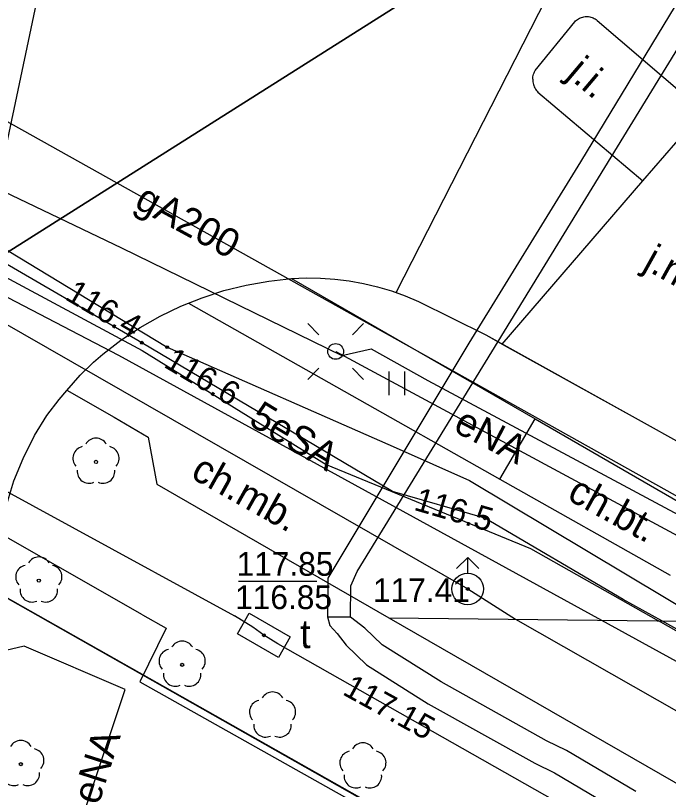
# Model space of a CAD drawing. Extents: x 6434771 to 6436222, y 5663454 to 5664782.
# Drawn here: x 6435079.09 to 6435099.76, y 5663940.88 to 5663965.39 of the extents above; entities that cross this region are included whole.
import ezdxf

# ---------------------------------------------------------------- set-up
doc = ezdxf.new("R2010")
doc.units = 0
for name, color, linetype in [('Warstwa 1', 7, 'Continuous'), ('Warstwa 10', 7, 'Continuous'), ('Warstwa 11', 7, 'Continuous'), ('Warstwa 12', 7, 'Continuous'), ('Warstwa 13', 7, 'Continuous'), ('Warstwa 14', 7, 'Continuous'), ('Warstwa 2', 7, 'Continuous'), ('Warstwa 4', 7, 'Continuous'), ('Warstwa 5', 7, 'Continuous'), ('Warstwa 6', 7, 'Continuous'), ('Warstwa 7', 7, 'Continuous'), ('Warstwa 8', 7, 'Continuous'), ('Warstwa 9', 7, 'Continuous')]:
    doc.layers.add(name, color=color, linetype=linetype)

msp = doc.modelspace()

# ---------------------------------------------------------------- linework, layer by layer
at = {"layer": 'Warstwa 1'}
for q in [(6435120.043, 5663983.972), (6435120.043, 5663983.972), (6435199.169, 5663878.85), (6435199.169, 5663878.85)]:
    msp.add_line((6435069.683, 5663952.11), q, dxfattribs=at)
at = {"layer": 'Warstwa 10'}
for points in [[(6434896.42, 5664071.06), (6434898.16, 5664073.03), (6434900.23, 5664072.06), (6434923.31, 5664061.23), (6434926.55, 5664059.81), (6434927.25, 5664060), (6434930.24, 5664058.57), (6434930.73, 5664057.88), (6434948.57, 5664048.49), (6434986.66, 5664027.63), (6435008.6, 5664015.27), (6435029.24, 5664003.72), (6435037.15, 5663998.25), (6435049.94, 5663990.19), (6435056.65, 5663985.18), (6435065.79, 5663976.31), (6435067.86, 5663972.11), (6435071.01, 5663962.36), (6435072.82, 5663959.6), (6435082.35, 5663954.64), (6435097.639, 5663946.244)], [(6435029.359, 5664004.111), (6435038.639, 5663997.479), (6435049.682, 5663991.014), (6435059.257, 5663983.908), (6435063.578, 5663979.846), (6435066.7, 5663975.848), (6435068.234, 5663972.039), (6435070.123, 5663963.685), (6435072.703, 5663960.364), (6435083.097, 5663954.788), (6435088.923, 5663951.177), (6435095.392, 5663948.519), (6435099.449, 5663946.22)], [(6435099.552, 5663946.221), (6435098.33, 5663946.9), (6435093.95, 5663949.47), (6435091.03, 5663950.32), (6435083.09, 5663955.03), (6435073.14, 5663960.81), (6435072.01, 5663961.77), (6435069.49, 5663965.07), (6435065.5, 5663971.7), (6435061.58, 5663976.4), (6435056.94, 5663981.63), (6435044.61, 5663991.64), (6435039.27, 5663995.38), (6435030.2, 5664000.49)], [(6435097.639, 5663946.244), (6435110.23, 5663939.33), (6435134.8, 5663925.67), (6435154.54, 5663914.28), (6435171.5, 5663904.82), (6435193.4, 5663892.21), (6435192.998, 5663890.805)], [(6435182.257, 5663838.676), (6435188.304, 5663849.448), (6435193.351, 5663858.439), (6435194.278, 5663859.798), (6435191.577, 5663860.571), (6435190.64, 5663861.662), (6435194.242, 5663871.739), (6435194.776, 5663876.163), (6435192.223, 5663879.254), (6435189.657, 5663881.265), (6435188.718, 5663882.987), (6435189.733, 5663885.054), (6435194.267, 5663892.79), (6435145.165, 5663920.315), (6435099.449, 5663946.22)], [(6435276.336, 5663842.501), (6435260.05, 5663851.86), (6435249.96, 5663857.64), (6435238.71, 5663863.53), (6435238.1, 5663863.95), (6435237.79, 5663864.33), (6435236.77, 5663866.27), (6435229, 5663870.99), (6435224.85, 5663875.36), (6435224.07, 5663876.18), (6435215.14, 5663881.13), (6435208.14, 5663884.9), (6435192.12, 5663893.65), (6435170.67, 5663905.68), (6435152.15, 5663915.89), (6435146.79, 5663915.59), (6435128.02, 5663926.23), (6435125.23, 5663931.72), (6435111.04, 5663939.84), (6435099.552, 5663946.221)]]:
    msp.add_lwpolyline(points, dxfattribs=at)
at = {"layer": 'Warstwa 11'}
for centre in [(6435081.638, 5663951.256), (6435079.828, 5663947.497), (6435084.366, 5663944.832), (6435079.257, 5663941.684)]:
    msp.add_circle(centre, 0.05, dxfattribs=at)
for centre, start, end in [((6435081.638, 5663951.631), 30.1471, 149.8529), ((6435081.281, 5663951.372), 102.1471, 221.8529), ((6435081.995, 5663951.372), 318.1471, 77.8529), ((6435081.418, 5663950.953), 174.1471, 293.8529), ((6435081.858, 5663950.953), 246.1471, 5.8529), ((6435079.828, 5663947.872), 30.1471, 149.8529), ((6435079.471, 5663947.613), 102.1471, 221.8529), ((6435080.185, 5663947.613), 318.1471, 77.8529), ((6435079.608, 5663947.194), 174.1471, 293.8529), ((6435080.048, 5663947.194), 246.1471, 5.8529), ((6435084.366, 5663945.207), 30.1471, 149.8529), ((6435084.009, 5663944.948), 102.1471, 221.8529), ((6435084.723, 5663944.948), 318.1471, 77.8529), ((6435084.146, 5663944.529), 174.1471, 293.8529), ((6435084.586, 5663944.529), 246.1471, 5.8529), ((6435079.257, 5663942.059), 30.1471, 149.8529), ((6435079.614, 5663941.8), 318.1471, 77.8529), ((6435079.037, 5663941.381), 174.1471, 293.8529), ((6435079.477, 5663941.381), 246.1471, 5.8529)]:
    msp.add_arc(centre, 0.375, start, end, dxfattribs=at)
at = {"layer": 'Warstwa 12'}
for points in [[(6435141, 5664096.944), (6435140.712, 5664094.875), (6435140.541, 5664077.81), (6435140.348, 5664058.843), (6435140.244, 5664037.853), (6435131.538, 5664021.545), (6435121.662, 5664002.962), (6435115.163, 5663990.896), (6435113.532, 5663987.769), (6435105.974, 5663975.592), (6435096.975, 5663960.761), (6435093.444, 5663955.018), (6435088.979, 5663947.571), (6435088.964, 5663946.347), (6435089.697, 5663946.338), (6435089.709, 5663947.336), (6435089.904, 5663947.79), (6435099.437, 5663963.329), (6435112.073, 5663983.894), (6435114.868, 5663988.39), (6435124.041, 5664005.528), (6435134.579, 5664025.286), (6435141.037, 5664037.344)], [(6434986.93, 5664031.717), (6434992.77, 5664028.437), (6435004.492, 5664021.894), (6435005.105, 5664018.185), (6435011.542, 5664014.684), (6435027.829, 5664005.549), (6435040.87, 5663998.248), (6435044.067, 5663996.463), (6435047.835, 5663993.916), (6435060.611, 5663984.964), (6435069.684, 5663978.472), (6435072.37, 5663972.912), (6435073.728, 5663967.815), (6435073.844, 5663967.084), (6435073.839, 5663962.379), (6435073.912, 5663958.232), (6435075.469, 5663957.501), (6435076.211, 5663957.1), (6435093.406, 5663947.233)], [(6435029.763, 5664005.454), (6435034.388, 5664002.299), (6435042.886, 5663996.481), (6435048.366, 5663992.784), (6435050.056, 5663992.458), (6435053.785, 5663989.318), (6435060.963, 5663983.658), (6435062.158, 5663982.516), (6435067.739, 5663976.436), (6435069.698, 5663972.561), (6435070.863, 5663972.195), (6435071.455, 5663970.037), (6435072.977, 5663964.049), (6435072.957, 5663962.572), (6435082.449, 5663958.039), (6435089.417, 5663954.626), (6435090.354, 5663954.835), (6435092.145, 5663953.831), (6435102.441, 5663948.316), (6435106.279, 5663946.137)], [(6435065.567, 5663979.291), (6435066.099, 5663979.065), (6435068.636, 5663973.044), (6435071.308, 5663958.281), (6435070.678, 5663955.808), (6435070.482, 5663955.351), (6435070.596, 5663954.809), (6435086.024, 5663946.382)], [(6435076.981, 5663977.987), (6435075.009, 5663964.166), (6435107.26, 5663946.125)], [(6435062.844, 5663975.005), (6435065.937, 5663971.01), (6435067.536, 5663968.978), (6435072.283, 5663961.757), (6435073.425, 5663961.235), (6435081.75, 5663956.189), (6435083.889, 5663954.89), (6435091.142, 5663951.702), (6435093.466, 5663950.667), (6435100.922, 5663946.202)], [(6435089.227, 5663954.754), (6435105.187, 5663946.15)], [(6435093.406, 5663947.233), (6435094.917, 5663946.274)], [(6435079.194, 5663933.129), (6435079.1, 5663933.665), (6435082.557, 5663944.054), (6435079.363, 5663945.423), (6435077.427, 5663944.966), (6435072.67, 5663946.544)], [(6435276.296, 5663839.122), (6435202.248, 5663880.463), (6435193.528, 5663885.439), (6435193.106, 5663885.714), (6435192.653, 5663885.899), (6435159.975, 5663904.455), (6435111.809, 5663931.659), (6435087.394, 5663945.495), (6435086.953, 5663945.766), (6435086.601, 5663946.025), (6435086.024, 5663946.382)], [(6435098.725, 5663940.821), (6435096.535, 5663942.118), (6435095.902, 5663942.428), (6435092.567, 5663944.288), (6435090.696, 5663945.465), (6435090.154, 5663945.991), (6435089.697, 5663946.338), (6435088.964, 5663946.347), (6435089.045, 5663946.075), (6435089.273, 5663945.821), (6435089.556, 5663945.455), (6435090.2, 5663944.833), (6435092.159, 5663943.6), (6435095.532, 5663941.718), (6435096.155, 5663941.414), (6435098.325, 5663940.127)], [(6435094.917, 5663946.274), (6435142.273, 5663919.31), (6435142.316, 5663919.287), (6435154.155, 5663912.836)]]:
    msp.add_lwpolyline(points, dxfattribs=at)
at = {"layer": 'Warstwa 13'}
for centre, start, end in [((6435087.227, 5663943.596), 30.1471, 149.8529), ((6435086.87, 5663943.337), 102.0477, 221.9513), ((6435087.584, 5663943.337), 318.0487, 77.9523), ((6435087.007, 5663942.918), 174.1984, 293.7229), ((6435087.447, 5663942.918), 246.2771, 5.6877), ((6435090.088, 5663941.985), 30.1471, 149.8529), ((6435089.731, 5663941.726), 102.0477, 221.9513), ((6435090.445, 5663941.726), 318.0487, 77.9523), ((6435089.868, 5663941.307), 174.1984, 293.7229), ((6435090.308, 5663941.307), 246.2771, 5.6877)]:
    msp.add_arc(centre, 0.375, start, end, dxfattribs=at)
at = {"layer": 'Warstwa 14'}
msp.add_line((6435086.149, 5663947.482), (6435088.624, 5663947.482), dxfattribs=at)
for centre in [(6435083.09, 5663955.03), (6435083.889, 5663954.89), (6435093.95, 5663949.47), (6435086.953, 5663945.766), (6435086.953, 5663945.766)]:
    msp.add_circle(centre, 0.045, dxfattribs=at)
at = {"layer": 'Warstwa 2'}
for points in [[(6435083.106, 5663946.417), (6435077.742, 5663949.472)], [(6435083.106, 5663946.417), (6435083.86, 5663945.988), (6435083.029, 5663944.288), (6435118.054, 5663924.603)]]:
    msp.add_lwpolyline(points, dxfattribs=at)
msp.add_circle((6435089.227, 5663954.754), 0.25, dxfattribs=at)
at = {"layer": 'Warstwa 4'}
for points in [[(6435088.697, 5663955.284), (6435088.343, 5663955.638)], [(6435089.757, 5663955.284), (6435090.111, 5663955.638)], [(6435088.697, 5663954.224), (6435088.343, 5663953.87)], [(6435089.757, 5663954.224), (6435090.111, 5663953.87)], [(6435093.052, 5663947.879), (6435093.406, 5663948.233)], [(6435093.76, 5663947.879), (6435093.406, 5663948.233)], [(6435093.406, 5663947.733), (6435093.406, 5663948.233)]]:
    msp.add_lwpolyline(points, dxfattribs=at)
msp.add_lwpolyline([(6435086.116, 5663945.813), (6435086.488, 5663946.464), (6435087.79, 5663945.719), (6435087.418, 5663945.068)], close=True, dxfattribs=at)
msp.add_circle((6435093.406, 5663947.233), 0.5, dxfattribs=at)
at = {"layer": 'Warstwa 5'}
for p, q in [((6435086.392, 5663956.856), (6435087.108, 5663956.983)), ((6435087.108, 5663956.983), (6435087.831, 5663957.061)), ((6435087.831, 5663957.061), (6435095.541, 5663952.617)), ((6435085.686, 5663956.68), (6435086.392, 5663956.856)), ((6435084.564, 5663956.284), (6435084.994, 5663956.456)), ((6435084.994, 5663956.456), (6435085.686, 5663956.68)), ((6435084.564, 5663956.284), (6435094.428, 5663950.711)), ((6435090.918, 5663953.368), (6435090.918, 5663954.118)), ((6435091.418, 5663953.368), (6435091.418, 5663954.118)), ((6435094.428, 5663950.711), (6435095.541, 5663952.617))]:
    msp.add_line(p, q, dxfattribs=at)
at = {"layer": 'Warstwa 6'}
for points in [[(6435199.169, 5663878.85), (6435069.683, 5663952.11), (6435070.435, 5663958.091), (6435069.483, 5663961.233), (6435068.325, 5663963.837), (6435062.043, 5663974.514), (6435058.095, 5663979.622), (6435055.831, 5663981.839), (6435050.759, 5663985.791), (6435026.957, 5664002.35), (6434999.334, 5664017.996), (6434991.09, 5664022.666), (6434980.58, 5664028.593), (6434951.952, 5664044.671), (6434942.859, 5664049.431), (6434933.864, 5664054.041), (6434925.132, 5664058.117), (6434918.181, 5664061.441), (6434909.328, 5664065.359), (6434902.911, 5664068.147), (6434896.533, 5664070.874)], [(6435305.06, 5663883.021), (6435273.017, 5663901.219), (6435268.258, 5663903.897), (6435244.547, 5663917.184), (6435243.096, 5663914.681), (6435163.64, 5663959.364), (6435156.428, 5663963.391), (6435120.043, 5663983.972), (6435069.683, 5663952.11), (6435199.169, 5663878.85)], [(6435081.849, 5663954.665), (6435082.426, 5663955.108), (6435083.032, 5663955.51), (6435083.664, 5663955.87), (6435084.319, 5663956.186), (6435084.994, 5663956.456), (6435085.686, 5663956.68), (6435086.392, 5663956.856), (6435087.108, 5663956.983), (6435087.831, 5663957.061)], [(6435087.831, 5663957.061), (6435088.288, 5663957.082), (6435088.746, 5663957.077), (6435089.203, 5663957.046), (6435089.658, 5663956.99), (6435090.109, 5663956.909), (6435090.555, 5663956.803), (6435090.994, 5663956.672), (6435091.425, 5663956.517), (6435091.847, 5663956.338)], [(6435091.847, 5663956.338), (6435093.976, 5663955.277), (6435098.798, 5663952.598), (6435100.211, 5663951.818), (6435101.536, 5663951.115), (6435104.703, 5663949.243), (6435106.032, 5663948.42), (6435107.739, 5663947.509), (6435110.04, 5663946.091)], [(6435078.616, 5663949.002), (6435078.849, 5663950.027), (6435079.035, 5663950.655), (6435079.334, 5663951.359), (6435079.688, 5663952.096), (6435080.078, 5663952.721), (6435080.474, 5663953.236), (6435080.712, 5663953.521), (6435081.141, 5663954.002), (6435081.558, 5663954.418), (6435081.849, 5663954.665)]]:
    msp.add_lwpolyline(points, dxfattribs=at)
msp.add_lwpolyline([(6435026.957, 5664002.35), (6435050.759, 5663985.791), (6435055.831, 5663981.839), (6435058.095, 5663979.622), (6435062.043, 5663974.514), (6435068.325, 5663963.837), (6435069.483, 5663961.233), (6435070.435, 5663958.091), (6435069.683, 5663952.11), (6435120.043, 5663983.972), (6435070.884, 5664005.038), (6435011.285, 5664038.642), (6434957.736, 5664068.872), (6434942.859, 5664049.431), (6434951.952, 5664044.671), (6434980.58, 5664028.593), (6434991.09, 5664022.666), (6434999.334, 5664017.996)], close=True, dxfattribs=at)
for centre in [(6435093.406, 5663947.233), (6435086.953, 5663945.766)]:
    msp.add_circle(centre, 0.045, dxfattribs=at)
at = {"layer": 'Warstwa 7'}
msp.add_lwpolyline([(6435092.414, 5663987.68), (6435084.106, 5663975.052), (6435081.187, 5663970.512), (6435080.599, 5663969.849), (6435075.668, 5663946.507)], dxfattribs=at)
at = {"layer": 'Warstwa 8'}
for p, q in [((6435091.144, 5663956.618), (6435099.409, 5663972.815)), ((6435091.144, 5663956.618), (6435099.409, 5663972.815)), ((6435096.881, 5663965.265), (6435096.912, 5663965.285)), ((6435096.881, 5663965.265), (6435096.912, 5663965.285)), ((6435096.912, 5663965.285), (6435096.945, 5663965.303)), ((6435096.912, 5663965.285), (6435096.945, 5663965.303)), ((6435096.945, 5663965.303), (6435096.979, 5663965.319)), ((6435096.945, 5663965.303), (6435096.979, 5663965.319)), ((6435096.979, 5663965.319), (6435097.014, 5663965.332)), ((6435096.979, 5663965.319), (6435097.014, 5663965.332)), ((6435097.014, 5663965.332), (6435097.05, 5663965.343)), ((6435097.014, 5663965.332), (6435097.05, 5663965.343)), ((6435097.05, 5663965.343), (6435097.086, 5663965.351)), ((6435097.05, 5663965.343), (6435097.086, 5663965.351)), ((6435097.086, 5663965.351), (6435097.123, 5663965.356)), ((6435097.086, 5663965.351), (6435097.123, 5663965.356)), ((6435097.123, 5663965.356), (6435097.16, 5663965.359)), ((6435097.123, 5663965.356), (6435097.16, 5663965.359)), ((6435097.16, 5663965.359), (6435097.198, 5663965.359)), ((6435097.16, 5663965.359), (6435097.198, 5663965.359)), ((6435097.198, 5663965.359), (6435097.235, 5663965.356)), ((6435097.198, 5663965.359), (6435097.235, 5663965.356)), ((6435097.235, 5663965.356), (6435097.272, 5663965.35)), ((6435097.235, 5663965.356), (6435097.272, 5663965.35)), ((6435097.272, 5663965.35), (6435097.308, 5663965.342)), ((6435097.272, 5663965.35), (6435097.308, 5663965.342)), ((6435097.308, 5663965.342), (6435097.344, 5663965.331)), ((6435097.308, 5663965.342), (6435097.344, 5663965.331)), ((6435097.344, 5663965.331), (6435097.379, 5663965.317)), ((6435097.344, 5663965.331), (6435097.379, 5663965.317)), ((6435097.379, 5663965.317), (6435097.412, 5663965.301)), ((6435097.379, 5663965.317), (6435097.412, 5663965.301)), ((6435097.412, 5663965.301), (6435097.445, 5663965.282)), ((6435097.412, 5663965.301), (6435097.445, 5663965.282)), ((6435097.445, 5663965.282), (6435097.476, 5663965.261)), ((6435097.445, 5663965.282), (6435097.476, 5663965.261)), ((6435095.542, 5663963.645), (6435096.798, 5663965.19)), ((6435095.542, 5663963.645), (6435096.798, 5663965.19)), ((6435096.798, 5663965.19), (6435096.824, 5663965.217)), ((6435096.798, 5663965.19), (6435096.824, 5663965.217)), ((6435096.824, 5663965.217), (6435096.852, 5663965.242)), ((6435096.824, 5663965.217), (6435096.852, 5663965.242)), ((6435096.852, 5663965.242), (6435096.881, 5663965.265)), ((6435096.852, 5663965.242), (6435096.881, 5663965.265)), ((6435097.476, 5663965.261), (6435097.505, 5663965.238)), ((6435097.476, 5663965.261), (6435097.505, 5663965.238)), ((6435097.505, 5663965.238), (6435100.854, 5663962.363)), ((6435097.505, 5663965.238), (6435100.854, 5663962.363)), ((6435095.491, 5663963.533), (6435095.505, 5663963.572)), ((6435095.491, 5663963.533), (6435095.505, 5663963.572)), ((6435095.505, 5663963.572), (6435095.522, 5663963.609)), ((6435095.505, 5663963.572), (6435095.522, 5663963.609)), ((6435095.522, 5663963.609), (6435095.542, 5663963.645)), ((6435095.522, 5663963.609), (6435095.542, 5663963.645)), ((6435095.464, 5663963.372), (6435095.466, 5663963.413)), ((6435095.464, 5663963.372), (6435095.466, 5663963.413)), ((6435095.464, 5663963.372), (6435095.464, 5663963.331)), ((6435095.464, 5663963.372), (6435095.464, 5663963.331)), ((6435095.464, 5663963.331), (6435095.468, 5663963.29)), ((6435095.464, 5663963.331), (6435095.468, 5663963.29)), ((6435095.466, 5663963.413), (6435095.471, 5663963.454)), ((6435095.466, 5663963.413), (6435095.471, 5663963.454)), ((6435095.471, 5663963.454), (6435095.48, 5663963.494)), ((6435095.471, 5663963.454), (6435095.48, 5663963.494)), ((6435095.48, 5663963.494), (6435095.491, 5663963.533)), ((6435095.48, 5663963.494), (6435095.491, 5663963.533)), ((6435095.468, 5663963.29), (6435095.475, 5663963.25)), ((6435095.468, 5663963.29), (6435095.475, 5663963.25)), ((6435095.475, 5663963.25), (6435095.484, 5663963.21)), ((6435095.475, 5663963.25), (6435095.484, 5663963.21)), ((6435095.484, 5663963.21), (6435095.497, 5663963.17)), ((6435095.484, 5663963.21), (6435095.497, 5663963.17)), ((6435095.497, 5663963.17), (6435095.512, 5663963.132)), ((6435095.497, 5663963.17), (6435095.512, 5663963.132)), ((6435095.512, 5663963.132), (6435095.53, 5663963.096)), ((6435095.512, 5663963.132), (6435095.53, 5663963.096)), ((6435095.53, 5663963.096), (6435095.551, 5663963.06)), ((6435095.53, 5663963.096), (6435095.551, 5663963.06)), ((6435095.551, 5663963.06), (6435095.574, 5663963.026)), ((6435095.551, 5663963.06), (6435095.574, 5663963.026)), ((6435095.574, 5663963.026), (6435095.6, 5663962.994)), ((6435095.574, 5663963.026), (6435095.6, 5663962.994)), ((6435095.6, 5663962.994), (6435095.628, 5663962.964)), ((6435095.6, 5663962.994), (6435095.628, 5663962.964)), ((6435095.628, 5663962.964), (6435098.953, 5663960.156)), ((6435095.628, 5663962.964), (6435098.953, 5663960.156)), ((6435098.953, 5663960.156), (6435100.854, 5663962.363)), ((6435098.953, 5663960.156), (6435100.854, 5663962.363)), ((6435094.5, 5663954.986), (6435098.953, 5663960.156)), ((6435094.5, 5663954.986), (6435098.953, 5663960.156)), ((6435086.392, 5663956.856), (6435087.108, 5663956.983)), ((6435087.108, 5663956.983), (6435087.831, 5663957.061)), ((6435087.831, 5663957.061), (6435088.288, 5663957.082)), ((6435088.288, 5663957.082), (6435088.746, 5663957.077)), ((6435088.746, 5663957.077), (6435089.203, 5663957.046)), ((6435089.203, 5663957.046), (6435089.658, 5663956.99)), ((6435089.658, 5663956.99), (6435090.109, 5663956.909)), ((6435085.686, 5663956.68), (6435086.392, 5663956.856)), ((6435090.109, 5663956.909), (6435090.555, 5663956.803)), ((6435090.555, 5663956.803), (6435090.994, 5663956.672)), ((6435084.319, 5663956.186), (6435084.994, 5663956.456)), ((6435084.994, 5663956.456), (6435085.686, 5663956.68)), ((6435090.994, 5663956.672), (6435091.144, 5663956.618)), ((6435091.144, 5663956.618), (6435091.425, 5663956.517)), ((6435091.425, 5663956.517), (6435091.847, 5663956.338)), ((6435091.847, 5663956.338), (6435093.976, 5663955.277)), ((6435083.664, 5663955.87), (6435084.319, 5663956.186)), ((6435083.032, 5663955.51), (6435083.664, 5663955.87)), ((6435082.426, 5663955.108), (6435083.032, 5663955.51)), ((6435093.976, 5663955.277), (6435094.5, 5663954.986)), ((6435081.849, 5663954.665), (6435082.426, 5663955.108)), ((6435094.5, 5663954.986), (6435098.798, 5663952.598)), ((6435081.558, 5663954.418), (6435081.849, 5663954.665)), ((6435081.141, 5663954.002), (6435081.558, 5663954.418)), ((6435080.716, 5663953.526), (6435081.141, 5663954.002)), ((6435080.474, 5663953.236), (6435080.712, 5663953.521)), ((6435080.712, 5663953.521), (6435080.716, 5663953.526)), ((6435080.078, 5663952.721), (6435080.474, 5663953.236)), ((6435079.688, 5663952.096), (6435080.078, 5663952.721)), ((6435098.798, 5663952.598), (6435100.211, 5663951.818)), ((6435079.334, 5663951.359), (6435079.688, 5663952.096)), ((6435079.035, 5663950.655), (6435079.334, 5663951.359))]:
    msp.add_line(p, q, dxfattribs=at)
at = {"layer": 'Warstwa 9'}
for p, q in [((6435087.831, 5663957.061), (6435088.288, 5663957.082)), ((6435087.831, 5663957.061), (6435095.541, 5663952.617)), ((6435088.288, 5663957.082), (6435088.746, 5663957.077)), ((6435088.746, 5663957.077), (6435089.203, 5663957.046)), ((6435089.203, 5663957.046), (6435089.658, 5663956.99)), ((6435089.658, 5663956.99), (6435090.109, 5663956.909)), ((6435090.109, 5663956.909), (6435090.555, 5663956.803)), ((6435090.555, 5663956.803), (6435090.994, 5663956.672)), ((6435090.994, 5663956.672), (6435091.144, 5663956.618)), ((6435091.144, 5663956.618), (6435091.425, 5663956.517)), ((6435091.425, 5663956.517), (6435091.847, 5663956.338)), ((6435084.319, 5663956.186), (6435084.564, 5663956.284)), ((6435084.564, 5663956.284), (6435094.428, 5663950.711)), ((6435091.847, 5663956.338), (6435093.976, 5663955.277)), ((6435083.664, 5663955.87), (6435084.319, 5663956.186)), ((6435083.032, 5663955.51), (6435083.664, 5663955.87)), ((6435082.426, 5663955.108), (6435083.032, 5663955.51)), ((6435093.976, 5663955.277), (6435094.5, 5663954.986)), ((6435081.849, 5663954.665), (6435082.426, 5663955.108)), ((6435094.5, 5663954.986), (6435098.798, 5663952.598)), ((6435081.558, 5663954.418), (6435081.849, 5663954.665)), ((6435081.141, 5663954.002), (6435081.558, 5663954.418)), ((6435080.716, 5663953.526), (6435081.141, 5663954.002)), ((6435080.716, 5663953.526), (6435082.212, 5663952.675)), ((6435082.212, 5663952.675), (6435083.293, 5663952.035)), ((6435094.428, 5663950.711), (6435095.541, 5663952.617)), ((6435095.541, 5663952.617), (6435100.875, 5663949.533)), ((6435095.541, 5663952.617), (6435100.875, 5663949.533)), ((6435098.798, 5663952.598), (6435100.211, 5663951.818)), ((6435083.293, 5663952.035), (6435083.565, 5663950.552)), ((6435094.428, 5663950.711), (6435099.812, 5663947.675)), ((6435094.428, 5663950.711), (6435099.812, 5663947.675)), ((6435083.565, 5663950.552), (6435090.91, 5663946.323)), ((6435090.91, 5663946.323), (6435102.437, 5663946.183)), ((6435090.91, 5663946.323), (6435102.437, 5663946.183)), ((6435090.91, 5663946.323), (6435135.707, 5663920.53))]:
    msp.add_line(p, q, dxfattribs=at)

# ---------------------------------------------------------------- texts
at = {"layer": 'Warstwa 11'}
msp.add_text('5eSA', height=0.9, rotation=328.9064, dxfattribs=at).set_placement((6435086.432, 5663952.459))
msp.add_text('5eSA', height=0.9, rotation=328.9064, dxfattribs=at).set_placement((6435086.432, 5663952.459))
msp.add_text('5eSA', height=0.9, rotation=328.9064, dxfattribs=at).set_placement((6435086.432, 5663952.459))
at = {"layer": 'Warstwa 13'}
for s, rotation, p in [('gA200', 331.4675, (6435082.813, 5663959.329)), ('eNA', 332.3671, (6435092.909, 5663952.246)), ('eNA', 72.2958, (6435081.715, 5663940.361))]:
    msp.add_text(s, height=0.9, rotation=rotation, dxfattribs=at).set_placement(p)
at = {"layer": 'Warstwa 14'}
for s, rotation, p in [('116.4', 329.4737, (6435080.623, 5663956.421)), ('116.6', 329.3247, (6435083.748, 5663954.281)), ('116.5', 343.7689, (6435091.669, 5663949.743)), ('117.15', 331.1524, (6435089.407, 5663943.909))]:
    msp.add_text(s, height=0.75, rotation=rotation, dxfattribs=at).set_placement(p)
msp.add_text('116.85', height=0.75, dxfattribs=at).set_placement((6435086.042, 5663946.595))
at = {"layer": 'Warstwa 5'}
msp.add_text('t', height=0.9, dxfattribs=at).set_placement((6435088.103, 5663945.359))
at = {"layer": 'Warstwa 6'}
for s, p in [('117.85', (6435086.087, 5663947.651)), ('117.41', (6435090.406, 5663946.821))]:
    msp.add_text(s, height=0.75, dxfattribs=at).set_placement(p)
at = {"layer": 'Warstwa 8'}
for s, rotation, p in [('j.i.', 319.8193, (6435096.506, 5663963.482)), ('j.mb.', 330.9462, (6435098.919, 5663957.398))]:
    msp.add_text(s, height=0.9, rotation=rotation, dxfattribs=at).set_placement(p)
at = {"layer": 'Warstwa 9'}
for s, rotation, p in [('ch.mb.', 330.7571, (6435084.596, 5663950.77)), ('ch.bt.', 331.2269, (6435096.515, 5663950.085))]:
    msp.add_text(s, height=0.9, rotation=rotation, dxfattribs=at).set_placement(p)

doc.saveas('drawing.dxf')
